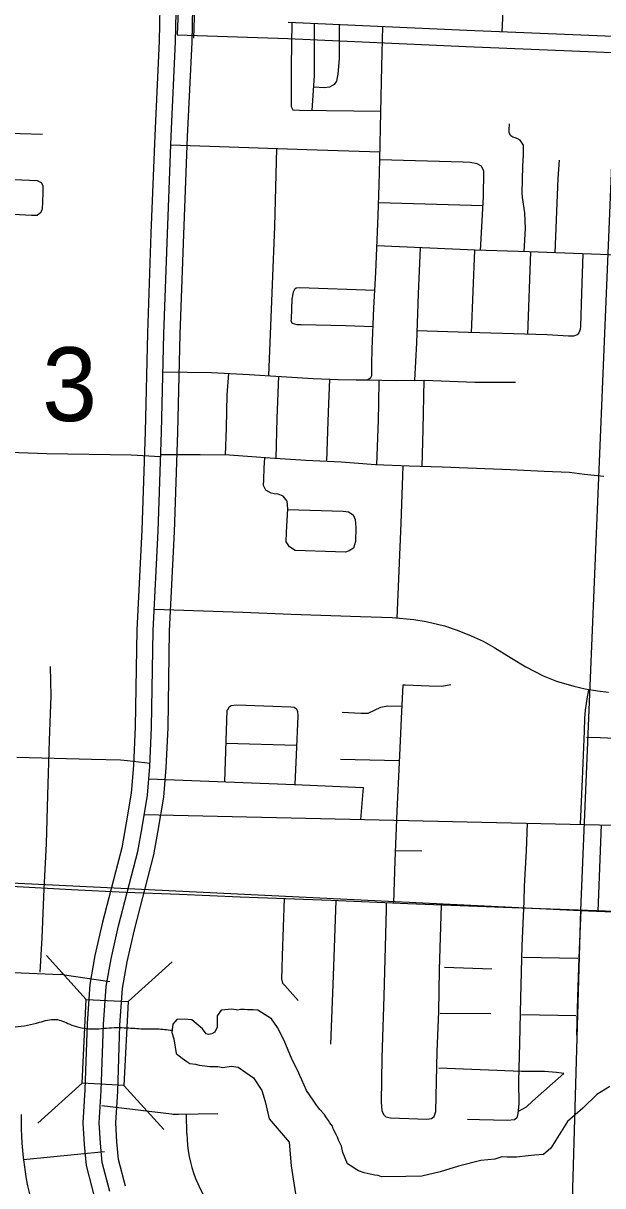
# Model space of a CAD drawing. Extents: x 1219626 to 1426462, y 456797 to 752399.
# Drawn here: x 1293754 to 1297287, y 526369 to 533458 of the extents above; entities that cross this region are included whole.
import ezdxf

# ---------------------------------------------------------------- set-up
doc = ezdxf.new("R2010")
doc.units = 0
for name, color, linetype in [('Bridges', 7, 'Continuous'), ('Lakes and Ponds', 7, 'Continuous'), ('Local Roads Paved', 7, 'Continuous'), ('Masks', 7, 'Continuous'), ('Narrow River Creek and Branch and Slough', 7, 'Continuous'), ('Section Lines', 7, 'Continuous'), ('Section Numbers', 7, 'Continuous'), ('State Route Divided Highway Outline and Fill', 7, 'Continuous'), ('State Routes Highway Center Lines', 7, 'Continuous')]:
    doc.layers.add(name, color=color, linetype=linetype)

msp = doc.modelspace()

# ---------------------------------------------------------------- linework, layer by layer
at = {"layer": 'Bridges'}
for p, q in [((1294138.1, 527505.8), (1293895.3, 527774.4)), ((1294393.8, 527493), (1294662.3, 527735.8)), ((1294112.4, 526994.5), (1293843.9, 526751.7)), ((1294368.1, 526981.6), (1294610.9, 526713.1))]:
    msp.add_line(p, q, dxfattribs=at)
msp.add_lwpolyline([(1294112.4, 526994.5), (1294138.1, 527505.8), (1294393.8, 527493), (1294368.1, 526981.6)], close=True, dxfattribs=at)
at = {"layer": 'Lakes and Ponds'}
msp.add_lwpolyline([(1297329.3, 526974.1), (1297251.8, 526925.3), (1297165.8, 526842), (1297071.1, 526761.7), (1296970.7, 526598), (1296924.8, 526560.7), (1296870.3, 526555), (1296833, 526552.1), (1296761.3, 526543.5), (1296703.9, 526543.5), (1296672.3, 526546.4), (1296629.3, 526532), (1296543.2, 526523.4), (1296408.4, 526489), (1296296.5, 526454.5), (1296184.6, 526428.7), (1296087.1, 526425.8), (1295937.9, 526423), (1295917.8, 526431.6), (1295897.8, 526434.4), (1295869.1, 526440.2), (1295831.8, 526448.8), (1295797.4, 526460.3), (1295777.3, 526471.8), (1295757.2, 526486.1), (1295731.4, 526503.3), (1295701.7, 526572.6), (1295693.5, 526610.8), (1295675.2, 526646.8), (1295670.8, 526665.4), (1295663.7, 526678.4), (1295643.6, 526715.7), (1295638.8, 526732.5), (1295623.5, 526753), (1295615.1, 526766.5), (1295603.8, 526783), (1295588.3, 526806.7), (1295562.6, 526834.6), (1295542, 526860.3), (1295521.3, 526892.3), (1295480.1, 526949.6), (1295452.3, 527015.6), (1295439.9, 527041.4), (1295428.6, 527069.2), (1295393.5, 527137.3), (1295344.1, 527254.2), (1295304.9, 527333.6), (1295266.8, 527388.2), (1295206.6, 527425.4), (1295183.9, 527439.8), (1295155, 527441.9), (1295135.5, 527442.9), (1295121, 527441.9), (1295102.5, 527443.9), (1295092.2, 527445), (1295078.8, 527443.9), (1295063.3, 527440.8), (1295053, 527441.9), (1295024.1, 527446), (1294982.9, 527441.9), (1294961.3, 527440.8), (1294936.5, 527405.8), (1294936.5, 527335.7), (1294923.1, 527306.8), (1294903.6, 527295.4), (1294882.9, 527291.3), (1294868.5, 527295.4), (1294847.9, 527326.4), (1294780.9, 527381), (1294734.5, 527386.2), (1294691.2, 527383.1), (1294666.5, 527355.2), (1294659.3, 527304.7), (1294671.6, 527265.5), (1294686.1, 527176.8), (1294722.1, 527148), (1294751, 527126.3), (1294770.6, 527115), (1294804.6, 527110.8), (1294826.2, 527104.7), (1294845.8, 527102.6), (1294891.2, 527097.4), (1294940.7, 527096.4), (1294971.6, 527091.2), (1295021.1, 527099.4), (1295065.2, 527092.4), (1295158, 527027.4), (1295209, 526950.9), (1295229.8, 526883.6), (1295253, 526776.8), (1295375.9, 526635.3), (1295387.5, 526491.4), (1295417.7, 526294.2)], dxfattribs=at)
at = {"layer": 'Local Roads Paved'}
for p, q in [((1293870.7, 532778.7), (1293565.5, 532789.4)), ((1295297.1, 532693.9), (1295286.2, 532218.6)), ((1295920.8, 532365.6), (1296557.1, 532347.3)), ((1296485.9, 531570.9), (1296507.9, 532073.8)), ((1296847.3, 532064.2), (1296828.3, 531560.9)), ((1294990.3, 529068.9), (1295420.4, 529056.5)), ((1295687.3, 528969.7), (1296046.3, 528962.5)), ((1294492, 528633.4), (1297479.8, 528566)), ((1297259.7, 528043.5), (1297278.9, 528570.5)), ((1296022.6, 528414.2), (1296184.9, 528411.4)), ((1296800.4, 527763.2), (1297134.9, 527756.9)), ((1293015.2, 527697), (1293983.5, 527658.3)), ((1296610.9, 527690.2), (1296322.7, 527699.8)), ((1294005.7, 527656.1), (1294281.4, 527614)), ((1296296.6, 527420.9), (1296605.6, 527419)), ((1296791.7, 527414.1), (1297122.8, 527407.4)), ((1294234.2, 526858.4), (1294658.7, 526807.4)), ((1294700.1, 526805.4), (1294941.4, 526809.9)), ((1294751.1, 526687.7), (1294748.8, 526806.3)), ((1294250.2, 526576.7), (1293755.4, 526526.6))]:
    msp.add_line(p, q, dxfattribs=at)
for points in [[(1296673.5, 533407.3), (1296692.8, 533770.4), (1296711.2, 534340.9), (1296732.5, 534946.1), (1296756.6, 535526.3), (1296750.8, 535567.9), (1296733.4, 535594.9), (1296696.7, 535615.2), (1296669.6, 535621), (1296596.1, 535622), (1296186.2, 535631.7), (1295977.3, 535630.7), (1295911.6, 535626.8), (1295861.3, 535619.1), (1295800.4, 535598.8), (1295743.3, 535572.7), (1295697.9, 535539.8), (1295652.4, 535490.5), (1295613.8, 535455.7), (1295588.6, 535444.1), (1295543.2, 535440.2), (1295520, 535441.2), (1294741.7, 535461.4)], [(1294605.8, 531332.7), (1294901.4, 531328), (1295131.5, 531316.4), (1295521.2, 531292.2), (1295673.9, 531286.4), (1295783.7, 531283), (1295853.8, 531284.5), (1295872.6, 531297.6), (1295879.9, 531310.6), (1295879.9, 531381.7), (1295881.3, 531470.1), (1295892, 531722), (1295903.6, 531938.6), (1295918.1, 532286.2), (1295924.4, 532471.9), (1295928.7, 532627), (1295934, 532916.1), (1295939.8, 533194.1), (1295945.7, 533439)], [(1295392, 533463.7), (1295386.5, 533194.4), (1295387, 532986), (1295387.5, 532949.3), (1295398.1, 532930.4), (1295437.3, 532927.5), (1295934.1, 532920.9)], [(1295516.2, 532926.5), (1295530.1, 533139.7), (1295530.6, 533327.3), (1295528.8, 533457.6)], [(1295681, 533450.8), (1295680.5, 533242.7), (1295672.7, 533147.5), (1295664.5, 533105.4), (1295648.6, 533084.1), (1295621, 533068.7), (1295591.5, 533064.8), (1295525.4, 533067.8)], [(1296808.5, 532065.4), (1296816.1, 532205.5), (1296811.3, 532301.2), (1296797.7, 532396), (1296795.8, 532421.1), (1296800.6, 532585.5), (1296804.5, 532655.1), (1296804.5, 532714.1), (1296784.2, 532745), (1296768.7, 532753.7), (1296753.2, 532758.5), (1296739.7, 532762.4), (1296727.1, 532772.1), (1296716.5, 532789.5), (1296716.5, 532806.9), (1296718.4, 532844.6)], [(1294654, 532715.6), (1295482.5, 532687.6), (1295929.6, 532673.4)], [(1296542.6, 532072.8), (1296559.9, 532399.8), (1296562.8, 532556.5), (1296547.3, 532585.5), (1296521.2, 532600.9), (1296479.6, 532609.6), (1296435.1, 532611.6), (1295928.7, 532625.5)], [(1296996.2, 532058.5), (1297016, 532511.6), (1297022.8, 532622.8)], [(1293553.7, 532510.9), (1293839.7, 532498.3), (1293863.9, 532487.7), (1293874.5, 532468.3), (1293874.5, 532428.7), (1293871.6, 532366.8), (1293869.7, 532326.2), (1293861, 532304.9), (1293839.7, 532286.6), (1293804, 532286.6), (1293544.7, 532299.1)], [(1295286.2, 532218.6), (1295271.7, 531865.7), (1295248.7, 531309.1)], [(1303094, 531819.7), (1302780.7, 531827.7), (1302459.2, 531835.4), (1302148.8, 531847.5), (1301837.4, 531860), (1301642.1, 531866.8), (1301226.4, 531887.1), (1300874.9, 531901.6), (1300622.1, 531912.7), (1300376.9, 531922.9), (1299925.4, 531940.8), (1299441.5, 531958.2), (1298886.9, 531979), (1298373.5, 532005.1), (1297838.3, 532026.4), (1297543, 532037.5), (1296838.1, 532064.5), (1296509.3, 532073.7), (1295910.3, 532099.7)], [(1296174, 532088.3), (1296162, 531808.8), (1296151.3, 531509.1), (1296139.8, 531280.9)], [(1297164.7, 532052), (1297156.9, 531811.7), (1297152.1, 531610.1), (1297149.2, 531589.8), (1297141.9, 531569.5), (1297130.3, 531557.4), (1297109.5, 531550.2), (1297077.2, 531549.2), (1296948.1, 531557.4), (1296469.5, 531571.4), (1296154, 531582.5)], [(1295897.6, 531827.6), (1295440.7, 531843.6), (1295418, 531842.6), (1295406.8, 531834.9), (1295400.1, 531817.5), (1295391.8, 531775.4), (1295386.5, 531655.1), (1295386, 531642.5), (1295393.8, 531629), (1295421.8, 531621.2), (1295448.4, 531621.2), (1295721.6, 531615.9), (1295887.2, 531609.3)], [(1294987.1, 530823.9), (1294992.8, 530991.5), (1294998.1, 531192.2), (1295007.9, 531322.6)], [(1295310.4, 531305.3), (1295300, 531050.3), (1295294, 530803.8)], [(1295604.8, 530786), (1295611.3, 530970.5), (1295615.7, 531086), (1295622.3, 531288.4)], [(1295853.8, 531284.5), (1296027.1, 531279.9), (1296199.7, 531281.4), (1296506.7, 531269.8), (1296754.2, 531269.3)], [(1295922.9, 531282.7), (1295920.3, 531136.3), (1295917.8, 531040.6), (1295906.7, 530765.8)], [(1296196.6, 531281.3), (1296189.5, 530980.2), (1296183.5, 530755.2)], [(1293383.8, 530851.9), (1293897.3, 530835), (1294412.1, 530825.3), (1294591.9, 530816.1)], [(1297294.2, 530694.9), (1297174.8, 530707), (1297084.9, 530717.7), (1296929.2, 530724.4), (1296724.7, 530734.1), (1296465.1, 530744.2), (1296308, 530751), (1296107.8, 530757.8), (1295900.9, 530766), (1295771.8, 530775.2), (1295692.1, 530781.5), (1295477.9, 530792.6), (1295256.5, 530806.1), (1295010.9, 530823.5), (1294832.5, 530825.9), (1294592.3, 530827.1)], [(1295411.2, 530242.7), (1295376.4, 530264.9), (1295358, 530295.8), (1295359.9, 530353.9), (1295366.7, 530497.9), (1295363.8, 530543.4), (1295338.7, 530573.3), (1295308.7, 530585.9), (1295284.5, 530587.8), (1295265.2, 530591.7), (1295232.3, 530610.1), (1295219.7, 530640.1), (1295220.7, 530673.9), (1295222.6, 530747.4), (1295227.2, 530808.2)], [(1296067.7, 530759.4), (1296055.1, 530406.8), (1296032.1, 529831.1)], [(1295366.5, 530493.4), (1295704.2, 530482.5), (1295737, 530478.6), (1295766, 530460.2), (1295778.6, 530432.2), (1295782.5, 530382.9), (1295779.6, 530298.7), (1295767, 530256.2), (1295741.9, 530240.7), (1295718.7, 530233), (1295657.7, 530234.9), (1295411.2, 530242.7)], [(1294552.9, 529884.6), (1295093.1, 529866.3), (1295387, 529855.7), (1295809.6, 529841.2), (1296003.9, 529833.4), (1296135.4, 529822.8), (1296210.8, 529809.3), (1296322, 529784.1), (1296400.3, 529757), (1296484.4, 529723.2), (1296558.9, 529689.4), (1296629.5, 529649.7), (1296731, 529585.9), (1296819, 529532.7), (1296924.4, 529478.6), (1297004.6, 529445.7), (1297111, 529414.8), (1297180.6, 529399.3), (1297255.1, 529386.7), (1297322.7, 529379.9)], [(1293918.1, 529536.5), (1293921.4, 529356.6), (1293912.7, 529084.9), (1293901.1, 528750.9), (1293893.9, 528455), (1293879.4, 528178.9), (1293866.8, 527881.6), (1293855.2, 527671.8)], [(1296360.9, 529423.8), (1296306.3, 529414.6), (1296229.4, 529416.6), (1296082.9, 529421.9), (1296068.4, 529421.9), (1296060.2, 529260.9), (1296045.7, 528950.5), (1296032.2, 528652.7), (1296020.1, 528351.5), (1296012.1, 528094.5)], [(1297199.5, 529392), (1297192.4, 529351.4), (1297179.3, 529270.2), (1297176.7, 529219), (1297173.8, 529141.6), (1297162.2, 528849.6), (1297148.8, 528573.5)], [(1294982.1, 528832.5), (1294997.1, 529268.6), (1295002.9, 529275.4), (1295009.7, 529288.9), (1295021.3, 529298.6), (1295056.1, 529301.5), (1295384.8, 529288.9), (1295405.1, 529287), (1295420.6, 529278.3), (1295426.4, 529261.9), (1295428.4, 529231.9), (1295417.7, 528996.9), (1295409, 528815.1)], [(1295697.7, 529257.5), (1295813, 529250.6), (1295856.3, 529251.4), (1295895.3, 529269.6), (1295934.3, 529287), (1295975.9, 529294.8), (1296061.9, 529293.7)], [(1300931.2, 528948.7), (1300108.4, 528981.1), (1299623, 529000.4), (1299115.4, 529023.6), (1298648.9, 529042.5), (1298157.7, 529062.8), (1297773.3, 529079.2), (1297272, 529100), (1297187.4, 529103.4)], [(1294526.9, 528943.3), (1294390.4, 528960.9), (1294346.4, 528964.8), (1294170.9, 528968.2), (1293715.5, 528981.7)], [(1294519.9, 528851.2), (1295408, 528815.2), (1295826.7, 528796.8), (1295810.9, 528603.6)], [(1296825.8, 528580.8), (1296819.7, 528411), (1296808.1, 528196.8), (1296805.7, 528105), (1296794.1, 527833.3), (1296786.4, 527512.3), (1296779.1, 527239.6), (1296774.3, 527006.1), (1296775.2, 526869.3), (1296769.4, 526809.3), (1296762.2, 526783.7), (1296748.7, 526772.1), (1296707.1, 526768.2), (1296535.9, 526770.7), (1296462.4, 526773.1)], [(1293680.7, 528195.9), (1294048.6, 528175.6), (1294379.7, 528159.1), (1294707.5, 528147), (1295075.9, 528131.6), (1295629.5, 528110.3), (1296097.9, 528091), (1296735.1, 528065.8), (1297028.1, 528055.2), (1297469.5, 528038.7), (1297627.6, 528036.8)], [(1295345.6, 528121.2), (1295331.7, 527771.9), (1295329.7, 527693.6), (1295327.8, 527631.7), (1295334.6, 527605.6), (1295348.1, 527591.1), (1295429.3, 527499.2)], [(1295628.5, 527233.3), (1295644.9, 527649.1), (1295661.8, 528109)], [(1295967, 528096.4), (1295966.4, 528053.7), (1295958.2, 527751.6), (1295952.4, 527525.3), (1295940.8, 527150.2), (1295936, 526879.4), (1295940.8, 526828.7), (1295949.5, 526804.5), (1295964.5, 526789.5), (1295994, 526784.2), (1296215.4, 526775.5), (1296242, 526779.8), (1296259.9, 526791.4), (1296269.1, 526821.9), (1296278.3, 527188.4), (1296287.4, 527429.1), (1296292.3, 527685.3), (1296304.4, 528082.8)], [(1297129.1, 527287.9), (1297135.4, 527521.9), (1297142.2, 527758.3), (1297154.5, 528050.5)], [(1296777.2, 526825.3), (1296823.1, 526850.4), (1296859.4, 526884.3), (1297049.8, 527054), (1297004.9, 527060.7), (1296932.4, 527065.1), (1296791.2, 527066.5), (1296288.4, 527085.9)]]:
    msp.add_lwpolyline(points, dxfattribs=at)
for centre, radius, start, end in [((1293975.5, 527458.4), 200, 81.30848, 87.70825), ((1295641.6, 526755.2), 1900, 178.55051, 220.51633), ((1294694.5, 527105.3), 300, 263.15383, 271.08147), ((1295550.9, 526702.8), 800, 181.08147, 221.16074)]:
    msp.add_arc(centre, radius, start, end, dxfattribs=at)
at = {"layer": 'Masks'}
msp.add_line((1294799.1, 533558.5), (1294792.6, 533366.8), dxfattribs=at)
at = {"layer": 'Narrow River Creek and Branch and Slough'}
msp.add_spline([(1290394.5, 527136.8), (1290469, 527142.6), (1290589.5, 527165.5), (1290664.1, 527194.2), (1290755.9, 527194.2), (1290801.8, 527182.8), (1290916.5, 527182.8), (1290991.1, 527205.7), (1291054.2, 527165.5), (1291082.8, 527079.4), (1291117.3, 527016.3), (1291186.1, 526987.6), (1291295.1, 527004.8), (1291346.7, 527033.5), (1291352.5, 527079.4), (1291352.5, 527108.1), (1291392.6, 527136.8), (1291461.5, 527125.4), (1291564.7, 527171.3), (1291610.6, 527205.7), (1291685.2, 527222.9), (1291759.8, 527205.7), (1291782.7, 527159.8), (1291840.1, 527125.4), (1291891.7, 527125.4), (1291937.6, 527119.6), (1291989.2, 527068), (1292046.6, 527050.7), (1292115.4, 527022), (1292149.8, 526999.1), (1292132.6, 526941.7), (1292144.1, 526907.2), (1292190, 526838.4), (1292212.9, 526792.5), (1292270.3, 526769.5), (1292299, 526792.5), (1292356.4, 526832.6), (1292436.7, 526844.1), (1292494, 526930.2), (1292511.3, 526976.1), (1292534.2, 526999.1), (1292557.1, 527004.8), (1292626, 527056.5), (1292654.7, 527079.4), (1292729.2, 527096.7), (1292786.6, 527108.1), (1292838.2, 527085.2), (1292907.1, 527056.5), (1292975.9, 527108.1), (1293021.8, 527171.3), (1293084.9, 527188.5), (1293159.5, 527194.2), (1293262.7, 527217.2), (1293366, 527222.9), (1293486.5, 527263.1), (1293589.7, 527320.5), (1293704.5, 527337.7), (1293853.6, 527366.4), (1293951.1, 527383.7), (1294037.2, 527355), (1294151.9, 527326.3), (1294278.1, 527332), (1294398.6, 527332), (1294496.1, 527326.3), (1294570.7, 527326.3), (1294661.1, 527317.4)], degree=3, dxfattribs=at)
at = {"layer": 'Section Lines'}
for p, q in [((1297371.9, 533374.6), (1297152.1, 528046.8)), ((1291851.8, 528305.1), (1297152.1, 528046.8)), ((1297152.2, 528050.6), (1296995.2, 522740.1)), ((1297152.1, 528046.8), (1302422.6, 527862.8))]:
    msp.add_line(p, q, dxfattribs=at)
at = {"layer": 'State Route Divided Highway Outline and Fill'}
msp.add_line((1294700.2, 533587), (1294693.5, 533387.1), dxfattribs=at)
for points in [[(1294595.9, 533976.2), (1294583.3, 533348.7), (1294556.2, 532773.3), (1294532.9, 532178), (1294511.5, 531567.9), (1294497, 530967.3), (1294476.6, 530366), (1294446.5, 529758.7), (1294436.8, 529167.6), (1294426.3, 528932.3), (1294412.2, 528762.7), (1294380, 528570.4), (1294354.6, 528429.2), (1294237.8, 527977.3), (1294191.3, 527773.7), (1294159.9, 527596.1), (1294143.9, 527358.2), (1294130.3, 526953.4), (1294117.4, 526753), (1294124.6, 526621.7), (1294137.3, 526493.1), (1294187.3, 526304.5)], [(1294377.8, 526366.2), (1294334.7, 526528.8), (1294324.1, 526637), (1294317.7, 526752.1), (1294330.1, 526943.6), (1294343.6, 527348.1), (1294358.7, 527571.9), (1294387.4, 527734), (1294432.1, 527930.1), (1294550.1, 528386.4), (1294577.1, 528536.2), (1294610.8, 528737.9), (1294625.9, 528919.5), (1294636.7, 529161.5), (1294646.4, 529752.1), (1294676.5, 530357.7), (1294696.9, 530961.5), (1294711.4, 531562), (1294732.7, 532170.6), (1294756, 532764.7), (1294783.2, 533342), (1294795.9, 533971.9)], [(1294693.5, 533387.1), (1295366.3, 533364.8), (1296453.6, 533316.3), (1297495.4, 533273.6), (1298588.8, 533220.2), (1299667, 533175.6), (1300692.6, 533129), (1301783.5, 533086.4), (1302075.5, 533063.5), (1302211.1, 533044.9), (1302357, 533015.2), (1302514.6, 532972)]]:
    msp.add_lwpolyline(points, dxfattribs=at)
at = {"layer": 'State Routes Highway Center Lines'}
for points in [[(1294282.6, 526335.3), (1294236, 526510.9), (1294224.3, 526629.3), (1294217.5, 526752.5), (1294230.2, 526948.5), (1294243.7, 527353.1), (1294259.3, 527584), (1294289.3, 527753.8), (1294334.9, 527953.7), (1294452.3, 528407.8), (1294478.5, 528553.3), (1294511.5, 528750.3), (1294526.1, 528925.9), (1294536.8, 529164.6), (1294546.5, 529755.4), (1294576.5, 530361.8), (1294596.9, 530964.4), (1294611.5, 531565), (1294632.8, 532174.3), (1294656.1, 532769), (1294683.3, 533345.4), (1294695.9, 533974.1)], [(1295370.2, 533464.7), (1296457.8, 533416.2), (1297499.9, 533373.5), (1298593.4, 533320.1), (1299671.3, 533275.5), (1300696.8, 533228.9), (1301789.3, 533186.2), (1302086.2, 533162.9), (1302227.9, 533143.5), (1302380.2, 533112.5), (1302543.2, 533067.9)]]:
    msp.add_lwpolyline(points, dxfattribs=at)

# ---------------------------------------------------------------- texts
at = {"layer": 'Section Numbers'}
msp.add_text('3', height=450, rotation=0.00035, dxfattribs=at).set_placement((1293869.4, 531032.1))

doc.saveas('drawing.dxf')
